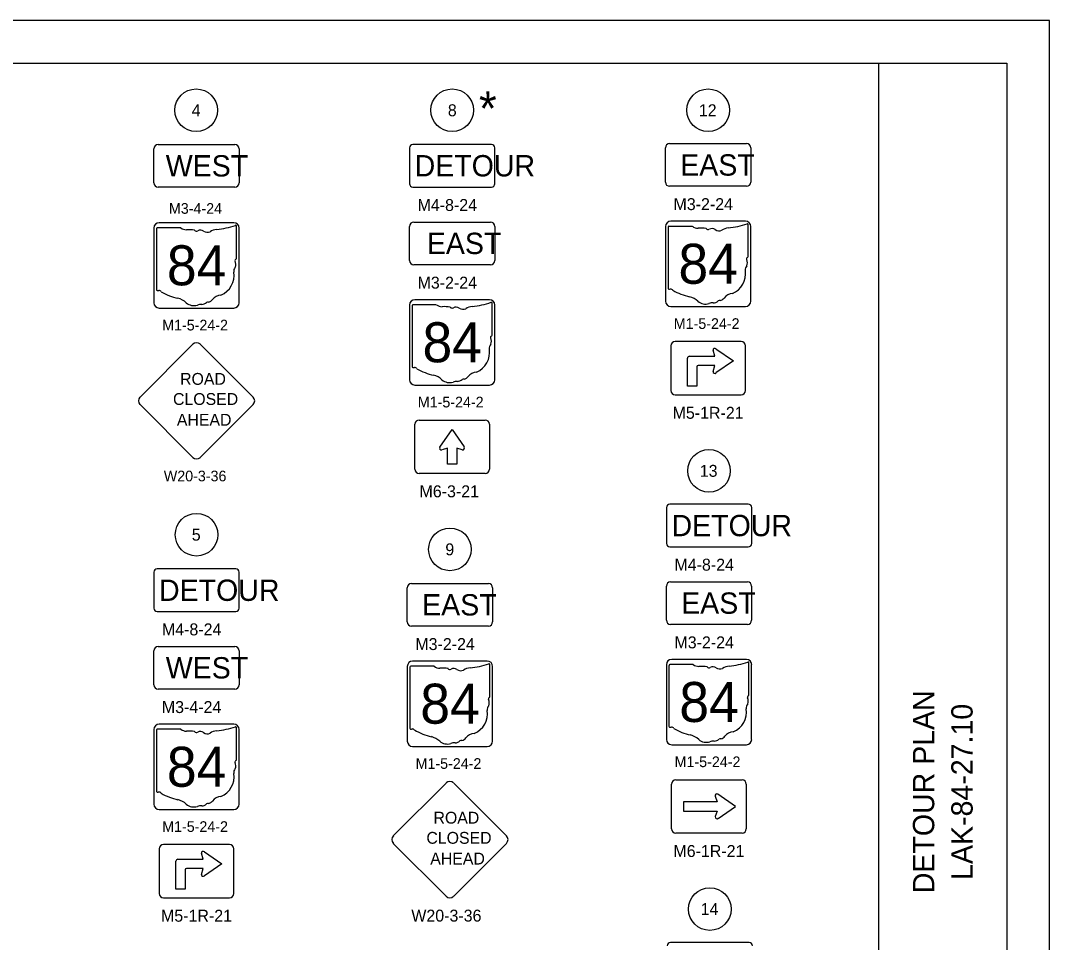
# Model space of a CAD drawing. Extents: x 0 to 54.8, y 0 to 22.
# Drawn here: x 21.94 to 34, y 11.2 to 22 of the extents above; entities that cross this region are included whole.
import ezdxf

# ---------------------------------------------------------------- set-up
doc = ezdxf.new("R2010")
doc.units = 0
for name, color, linetype in [('GM_X_Adjacent_County', 7, 'Continuous'), ('GM_X_County', 7, 'Continuous'), ('GM_X_County_Road', 7, 'Continuous'), ('GM_X_Minor_River_Text', 7, 'Continuous'), ('GM_X_Township', 7, 'Continuous')]:
    doc.layers.add(name, color=color, linetype=linetype)

msp = doc.modelspace()

# ---------------------------------------------------------------- linework, layer by layer
at = {"layer": 'GM_X_County'}
msp.add_lwpolyline([(0, 0), (34, 0), (34, 22), (0, 22)], close=True, dxfattribs=at)
at = {"layer": 'GM_X_County_Road'}
for centre in [(24, 20.949), (27, 20.949), (30, 20.949), (30.01, 16.724), (24.004, 15.976), (26.974, 15.804), (30.02, 11.589)]:
    msp.add_circle(centre, 0.25, dxfattribs=at)
at = {"layer": 'GM_X_Minor_River_Text'}
for p, q in [((23.554, 20.548), (24.454, 20.548)), ((29.499, 20.108), (29.499, 20.508)), ((29.549, 20.558), (30.449, 20.558)), ((30.499, 20.508), (30.499, 20.108)), ((23.504, 20.098), (23.504, 20.498)), ((24.504, 20.498), (24.504, 20.098)), ((24.454, 20.048), (23.554, 20.048)), ((30.449, 20.058), (29.549, 20.058)), ((23.534, 19.559), (23.534, 18.848)), ((23.818, 19.571), (23.544, 19.571)), ((24.472, 19.217), (24.472, 19.589)), ((26.5, 19.189), (26.5, 19.589)), ((26.55, 19.639), (27.45, 19.639)), ((27.5, 19.589), (27.5, 19.189)), ((29.531, 19.577), (29.531, 18.865)), ((29.814, 19.589), (29.54, 19.589)), ((30.468, 19.235), (30.468, 19.607)), ((24.472, 19.217), (24.472, 19.217)), ((30.468, 19.235), (30.468, 19.235)), ((27.45, 19.139), (26.55, 19.139)), ((26.531, 18.657), (26.531, 17.945)), ((26.814, 18.669), (26.54, 18.669)), ((27.468, 18.315), (27.468, 18.687)), ((27.468, 18.315), (27.468, 18.315)), ((30.387, 18.239), (29.612, 18.239)), ((29.562, 18.189), (29.562, 17.664)), ((30.078, 18.067), (30.057, 18.137)), ((30.092, 18.152), (30.296, 18.013)), ((30.437, 17.664), (30.437, 18.189)), ((29.757, 17.716), (29.757, 18.044)), ((29.781, 18.067), (30.078, 18.067)), ((29.781, 18.067), (29.781, 18.067)), ((30.296, 18.013), (30.092, 17.873)), ((29.867, 17.942), (29.867, 17.716)), ((30.078, 17.958), (29.882, 17.958)), ((30.057, 17.887), (30.078, 17.958)), ((29.612, 17.614), (30.387, 17.614)), ((29.867, 17.716), (29.757, 17.716)), ((26.562, 16.744), (26.562, 17.269)), ((26.612, 17.319), (27.387, 17.319)), ((27.437, 17.269), (27.437, 16.744)), ((26.857, 17.003), (26.999, 17.21)), ((26.999, 17.21), (27.139, 17.006)), ((26.945, 16.991), (26.881, 16.971)), ((26.945, 16.803), (26.945, 16.991)), ((27.118, 16.971), (27.054, 16.991)), ((27.054, 16.991), (27.054, 16.803)), ((27.054, 16.803), (26.945, 16.803)), ((27.387, 16.694), (26.612, 16.694)), ((26.474, 14.954), (26.474, 15.354)), ((26.524, 15.404), (27.424, 15.404)), ((27.474, 15.354), (27.474, 14.954)), ((29.51, 14.974), (29.51, 15.374)), ((29.56, 15.424), (30.46, 15.424)), ((30.51, 15.374), (30.51, 14.974)), ((27.424, 14.904), (26.524, 14.904)), ((30.46, 14.924), (29.56, 14.924)), ((23.504, 14.216), (23.504, 14.616)), ((23.554, 14.666), (24.454, 14.666)), ((24.504, 14.616), (24.504, 14.216)), ((30.478, 14.1), (30.478, 14.472)), ((26.504, 14.422), (26.504, 13.71)), ((26.788, 14.434), (26.514, 14.434)), ((27.442, 14.08), (27.442, 14.452)), ((29.541, 14.442), (29.541, 13.73)), ((29.825, 14.454), (29.55, 14.454)), ((24.454, 14.166), (23.554, 14.166)), ((27.442, 14.08), (27.442, 14.08)), ((30.478, 14.1), (30.478, 14.1)), ((23.534, 13.684), (23.534, 12.972)), ((23.818, 13.696), (23.544, 13.696)), ((24.472, 13.341), (24.472, 13.714)), ((24.472, 13.341), (24.472, 13.341)), ((29.572, 12.529), (29.572, 13.054)), ((29.622, 13.104), (30.397, 13.104)), ((30.447, 13.054), (30.447, 12.529)), ((30.084, 12.91), (30.104, 12.846)), ((30.322, 12.792), (30.115, 12.934)), ((30.104, 12.846), (29.713, 12.846)), ((29.713, 12.846), (29.713, 12.737)), ((30.118, 12.652), (30.322, 12.792)), ((29.713, 12.737), (30.104, 12.737)), ((30.104, 12.737), (30.084, 12.673)), ((30.397, 12.479), (29.622, 12.479)), ((24.391, 12.346), (23.616, 12.346)), ((23.566, 12.296), (23.566, 11.771)), ((24.081, 12.174), (24.061, 12.244)), ((24.096, 12.259), (24.3, 12.119)), ((24.441, 11.771), (24.441, 12.296)), ((23.761, 11.822), (23.761, 12.15)), ((23.785, 12.174), (24.081, 12.174)), ((23.785, 12.174), (23.785, 12.174)), ((24.081, 12.064), (23.886, 12.064)), ((24.061, 11.994), (24.081, 12.064)), ((24.3, 12.119), (24.096, 11.979)), ((23.871, 12.049), (23.871, 11.822)), ((23.871, 11.822), (23.761, 11.822)), ((23.616, 11.721), (24.391, 11.721))]:
    msp.add_line(p, q, dxfattribs=at)
for points in [[(26.5, 20.509), (26.5, 20.089)], [(27.46, 20.549), (26.54, 20.549)], [(27.5, 20.089), (27.5, 20.509)], [(26.54, 20.049), (27.46, 20.049)], [(23.504, 19.569), (23.504, 18.694)], [(24.441, 19.631), (23.566, 19.631)], [(24.504, 18.694), (24.504, 19.569)], [(29.5, 19.587), (29.5, 18.712)], [(30.438, 19.649), (29.562, 19.649)], [(30.5, 18.712), (30.5, 19.587)], [(27.438, 18.729), (26.562, 18.729)], [(23.566, 18.631), (24.441, 18.631)], [(26.5, 18.667), (26.5, 17.792)], [(27.5, 17.792), (27.5, 18.667)], [(29.562, 18.649), (30.438, 18.649)], [(23.341, 17.589), (23.96, 18.207)], [(24.048, 18.207), (24.667, 17.589)], [(26.562, 17.729), (27.438, 17.729)], [(23.96, 16.882), (23.341, 17.5)], [(24.667, 17.5), (24.048, 16.882)], [(29.511, 16.293), (29.511, 15.873)], [(30.471, 16.333), (29.551, 16.333)], [(30.511, 15.873), (30.511, 16.293)], [(29.551, 15.833), (30.471, 15.833)], [(24.463, 15.575), (23.543, 15.575)], [(23.503, 15.535), (23.503, 15.115)], [(24.503, 15.115), (24.503, 15.535)], [(23.543, 15.075), (24.463, 15.075)], [(27.411, 14.494), (26.536, 14.494)], [(30.448, 14.514), (29.573, 14.514)], [(26.474, 14.432), (26.474, 13.557)], [(27.474, 13.557), (27.474, 14.432)], [(29.51, 14.452), (29.51, 13.577)], [(30.51, 13.577), (30.51, 14.452)], [(24.441, 13.756), (23.566, 13.756)], [(23.504, 13.693), (23.504, 12.818)], [(24.504, 12.818), (24.504, 13.693)], [(29.573, 13.514), (30.448, 13.514)], [(26.536, 13.494), (27.411, 13.494)], [(26.31, 12.447), (26.929, 13.066)], [(27.018, 13.066), (27.636, 12.447)], [(23.566, 12.756), (24.441, 12.756)], [(26.929, 11.74), (26.31, 12.359)], [(27.636, 12.359), (27.018, 11.74)], [(30.48, 11.198), (29.56, 11.198)]]:
    msp.add_lwpolyline(points, dxfattribs=at)
for centre, radius, start, end in [((23.554, 20.498), 0.05, 90, 180), ((24.454, 20.498), 0.05, 0, 90), ((26.54, 20.509), 0.04, 90, 180), ((27.46, 20.509), 0.04, 0, 90), ((29.549, 20.508), 0.05, 90, 180), ((30.449, 20.508), 0.05, 0, 90), ((23.554, 20.098), 0.05, 180, 270), ((24.454, 20.098), 0.05, 270, 0), ((26.54, 20.089), 0.04, 180, 270), ((27.46, 20.089), 0.04, 270, 0), ((29.549, 20.108), 0.05, 180, 270), ((30.449, 20.108), 0.05, 270, 0), ((23.566, 19.569), 0.0625, 90, 180), ((23.545, 19.561), 0.0109, 98.1301, 188.1301), ((23.884, 19.654), 0.105, 231.6195, 271.1119), ((23.919, 19.172), 0.378, 80.4867, 94.9883), ((24.004, 19.564), 0.0304, 219.7921, 297.1024), ((24.049, 19.482), 0.0632, 54.4667, 119.1411), ((24.265, 19.354), 0.2, 97.3462, 120.7689), ((24.138, 20.541), 0.994, 275.8445, 288.9065), ((24.441, 19.569), 0.0625, 0, 90), ((24.462, 19.591), 0.0104, 351.8621, 97.738), ((26.55, 19.589), 0.05, 90, 180), ((27.45, 19.589), 0.05, 0, 90), ((29.562, 19.587), 0.0625, 90, 180), ((29.541, 19.579), 0.0109, 98.1301, 188.1301), ((29.88, 19.672), 0.105, 231.6195, 271.1119), ((29.915, 19.19), 0.378, 80.4867, 94.9883), ((30, 19.582), 0.0304, 219.7921, 297.1024), ((30.045, 19.5), 0.0632, 54.4667, 119.1411), ((30.127, 19.613), 0.076, 233.8562, 294.8282), ((30.261, 19.372), 0.2, 97.3462, 120.7689), ((30.134, 20.559), 0.994, 275.8445, 288.9065), ((30.438, 19.587), 0.0625, 0, 90), ((30.458, 19.608), 0.0104, 351.8621, 97.738), ((24.131, 19.595), 0.076, 233.8562, 294.8282), ((24.47, 19.189), 0.0162, 107.944, 210.337), ((24.367, 19.142), 0.097, 340.033, 23.6496), ((24.461, 19.215), 0.0112, 289.6038, 7.7341), ((26.55, 19.189), 0.05, 180, 270), ((27.45, 19.189), 0.05, 270, 0), ((30.466, 19.207), 0.0162, 107.944, 210.337), ((30.363, 19.16), 0.097, 340.033, 23.6496), ((30.457, 19.233), 0.0112, 289.6038, 7.7341), ((24.509, 19.061), 0.0705, 136.8065, 186.9296), ((30.19, 19.032), 0.249, 292.3089, 8.9858), ((30.505, 19.079), 0.0705, 136.8065, 186.9296), ((24.194, 19.014), 0.249, 292.3089, 8.9858), ((23.545, 18.846), 0.011, 171.9584, 258.3066), ((23.547, 18.919), 0.0836, 267.339, 280.6039), ((23.564, 18.807), 0.0302, 29.7484, 93.2717), ((23.945, 19.446), 0.718, 240.4129, 257.1985), ((29.541, 18.864), 0.011, 171.9584, 258.3066), ((29.543, 18.937), 0.0836, 267.339, 280.6039), ((29.56, 18.824), 0.0302, 29.7484, 93.2717), ((29.941, 19.464), 0.718, 240.4129, 257.1985), ((23.566, 18.694), 0.0625, 180, 270), ((23.731, 18.528), 0.225, 47.1842, 75.836), ((23.974, 18.803), 0.143, 230.7004, 286.2918), ((24.066, 18.75), 0.0759, 268.777, 315.5493), ((24.135, 18.681), 0.0214, 65.7517, 132.6484), ((24.126, 18.779), 0.0803, 282.8732, 323.2771), ((24.299, 18.648), 0.136, 94.4031, 142.5768), ((24.441, 18.694), 0.0625, 270, 0), ((26.562, 18.667), 0.0625, 90, 180), ((27.134, 19.639), 0.994, 275.8445, 288.9065), ((27.438, 18.667), 0.0625, 0, 90), ((27.458, 18.688), 0.0104, 351.8621, 97.738), ((29.562, 18.712), 0.0625, 180, 270), ((29.727, 18.546), 0.225, 47.1842, 75.836), ((29.97, 18.821), 0.143, 230.7004, 286.2918), ((30.052, 18.575), 0.117, 85.6951, 111.2099), ((30.062, 18.768), 0.0759, 268.777, 315.5493), ((30.131, 18.699), 0.0214, 65.7517, 132.6484), ((30.122, 18.797), 0.0803, 282.8732, 323.2771), ((30.295, 18.666), 0.136, 94.4031, 142.5768), ((30.438, 18.712), 0.0625, 270, 0), ((24.056, 18.557), 0.117, 85.6951, 111.2099), ((26.541, 18.659), 0.0109, 98.1301, 188.1301), ((26.88, 18.752), 0.105, 231.6195, 271.1119), ((26.915, 18.27), 0.378, 80.4867, 94.9883), ((27, 18.662), 0.0304, 219.7921, 297.1024), ((27.045, 18.58), 0.0632, 54.4667, 119.1411), ((27.127, 18.693), 0.076, 233.8562, 294.8282), ((27.261, 18.452), 0.2, 97.3462, 120.7689), ((24.004, 18.163), 0.0625, 45, 135), ((27.466, 18.287), 0.0162, 107.944, 210.337), ((27.363, 18.24), 0.097, 340.033, 23.6496), ((27.457, 18.313), 0.0112, 289.6038, 7.7341), ((29.612, 18.189), 0.05, 90, 180), ((30.387, 18.189), 0.05, 0, 90), ((27.19, 18.112), 0.249, 292.3089, 8.9858), ((27.505, 18.159), 0.0705, 136.8065, 186.9296), ((30.078, 18.137), 0.0209, 45.0001, 179.9983), ((29.781, 18.044), 0.0234, 90, 180), ((26.541, 17.944), 0.011, 171.9584, 258.3066), ((26.543, 18.017), 0.0836, 267.339, 280.6039), ((26.56, 17.904), 0.0302, 29.7484, 93.2717), ((26.941, 18.544), 0.718, 240.4129, 257.1985), ((27.295, 17.746), 0.136, 94.4031, 142.5768), ((29.882, 17.942), 0.0156, 90, 180), ((30.078, 17.887), 0.0209, 179.9983, 314.9999), ((26.562, 17.792), 0.0625, 180, 270), ((26.727, 17.626), 0.225, 47.1842, 75.836), ((26.97, 17.901), 0.143, 230.7004, 286.2918), ((27.052, 17.655), 0.117, 85.6951, 111.2099), ((27.062, 17.848), 0.0759, 268.777, 315.5493), ((27.131, 17.779), 0.0214, 65.7517, 132.6484), ((27.122, 17.877), 0.0803, 282.8732, 323.2771), ((27.438, 17.792), 0.0625, 270, 0), ((29.612, 17.664), 0.05, 180, 270), ((30.387, 17.664), 0.05, 270, 0), ((23.385, 17.545), 0.0625, 135, 225), ((24.623, 17.545), 0.0625, 315, 45), ((26.612, 17.269), 0.05, 90, 180), ((27.387, 17.269), 0.05, 0, 90), ((27.124, 16.991), 0.0209, 252.7954, 45.0096), ((26.874, 16.991), 0.0209, 145.4112, 287.2046), ((24.004, 16.926), 0.0625, 225, 315), ((26.612, 16.744), 0.05, 180, 270), ((27.387, 16.744), 0.05, 270, 0), ((29.551, 16.293), 0.04, 90, 180), ((30.471, 16.293), 0.04, 0, 90), ((29.551, 15.873), 0.04, 180, 270), ((30.471, 15.873), 0.04, 270, 0), ((23.543, 15.535), 0.04, 90, 180), ((24.463, 15.535), 0.04, 0, 90), ((26.524, 15.354), 0.05, 90, 180), ((27.424, 15.354), 0.05, 0, 90), ((29.56, 15.374), 0.05, 90, 180), ((30.46, 15.374), 0.05, 0, 90), ((23.543, 15.115), 0.04, 180, 270), ((24.463, 15.115), 0.04, 270, 0), ((26.524, 14.954), 0.05, 180, 270), ((27.424, 14.954), 0.05, 270, 0), ((29.56, 14.974), 0.05, 180, 270), ((30.46, 14.974), 0.05, 270, 0), ((23.554, 14.616), 0.05, 90, 180), ((24.454, 14.616), 0.05, 0, 90), ((26.536, 14.432), 0.0625, 90, 180), ((27.411, 14.432), 0.0625, 0, 90), ((29.573, 14.452), 0.0625, 90, 180), ((30.144, 15.424), 0.994, 275.8445, 288.9065), ((30.448, 14.452), 0.0625, 0, 90), ((30.468, 14.473), 0.0104, 351.8621, 97.738), ((26.515, 14.424), 0.0109, 98.1301, 188.1301), ((26.854, 14.517), 0.105, 231.6195, 271.1119), ((26.889, 14.035), 0.378, 80.4867, 94.9883), ((26.974, 14.427), 0.0304, 219.7921, 297.1024), ((27.019, 14.345), 0.0632, 54.4667, 119.1411), ((27.101, 14.458), 0.076, 233.8562, 294.8282), ((27.235, 14.217), 0.2, 97.3462, 120.7689), ((27.108, 15.404), 0.994, 275.8445, 288.9065), ((27.432, 14.453), 0.0104, 351.8621, 97.738), ((29.552, 14.444), 0.0109, 98.1301, 188.1301), ((29.89, 14.537), 0.105, 231.6195, 271.1119), ((29.925, 14.055), 0.378, 80.4867, 94.9883), ((30.011, 14.447), 0.0304, 219.7921, 297.1024), ((30.056, 14.365), 0.0632, 54.4667, 119.1411), ((30.137, 14.478), 0.076, 233.8562, 294.8282), ((30.271, 14.237), 0.2, 97.3462, 120.7689), ((23.554, 14.216), 0.05, 180, 270), ((24.454, 14.216), 0.05, 270, 0), ((27.44, 14.052), 0.0162, 107.944, 210.337), ((27.337, 14.005), 0.097, 340.033, 23.6496), ((27.431, 14.078), 0.0112, 289.6038, 7.7341), ((30.516, 13.944), 0.0705, 136.8065, 186.9296), ((30.476, 14.072), 0.0162, 107.944, 210.337), ((30.373, 14.025), 0.097, 340.033, 23.6496), ((30.467, 14.098), 0.0112, 289.6038, 7.7341), ((27.164, 13.877), 0.249, 292.3089, 8.9858), ((27.479, 13.924), 0.0705, 136.8065, 186.9296), ((30.2, 13.897), 0.249, 292.3089, 8.9858), ((23.566, 13.693), 0.0625, 90, 180), ((24.441, 13.693), 0.0625, 0, 90), ((23.545, 13.685), 0.0109, 98.1301, 188.1301), ((23.884, 13.779), 0.105, 231.6195, 271.1119), ((23.919, 13.297), 0.378, 80.4867, 94.9883), ((24.004, 13.689), 0.0304, 219.7921, 297.1024), ((24.049, 13.607), 0.0632, 54.4667, 119.1411), ((24.131, 13.719), 0.076, 233.8562, 294.8282), ((24.265, 13.479), 0.2, 97.3462, 120.7689), ((24.138, 14.666), 0.994, 275.8445, 288.9065), ((24.462, 13.715), 0.0104, 351.8621, 97.738), ((26.515, 13.709), 0.011, 171.9584, 258.3066), ((26.517, 13.782), 0.0836, 267.339, 280.6039), ((26.534, 13.669), 0.0302, 29.7484, 93.2717), ((26.915, 14.309), 0.718, 240.4129, 257.1985), ((27.269, 13.511), 0.136, 94.4031, 142.5768), ((29.552, 13.729), 0.011, 171.9584, 258.3066), ((29.553, 13.802), 0.0836, 267.339, 280.6039), ((29.571, 13.689), 0.0302, 29.7484, 93.2717), ((29.951, 14.329), 0.718, 240.4129, 257.1985), ((29.737, 13.411), 0.225, 47.1842, 75.836), ((30.305, 13.531), 0.136, 94.4031, 142.5768), ((26.536, 13.557), 0.0625, 180, 270), ((26.701, 13.391), 0.225, 47.1842, 75.836), ((26.944, 13.666), 0.143, 230.7004, 286.2918), ((27.026, 13.42), 0.117, 85.6951, 111.2099), ((27.036, 13.613), 0.0759, 268.777, 315.5493), ((27.105, 13.544), 0.0214, 65.7517, 132.6484), ((27.096, 13.642), 0.0803, 282.8732, 323.2771), ((27.411, 13.557), 0.0625, 270, 0), ((29.573, 13.577), 0.0625, 180, 270), ((29.98, 13.686), 0.143, 230.7004, 286.2918), ((30.062, 13.44), 0.117, 85.6951, 111.2099), ((30.073, 13.633), 0.0759, 268.777, 315.5493), ((30.142, 13.564), 0.0214, 65.7517, 132.6484), ((30.132, 13.662), 0.0803, 282.8732, 323.2771), ((30.448, 13.577), 0.0625, 270, 0), ((24.47, 13.314), 0.0162, 107.944, 210.337), ((24.367, 13.267), 0.097, 340.033, 23.6496), ((24.461, 13.34), 0.0112, 289.6038, 7.7341), ((24.194, 13.138), 0.249, 292.3089, 8.9858), ((24.509, 13.186), 0.0705, 136.8065, 186.9296), ((26.973, 13.022), 0.0625, 45, 135), ((29.622, 13.054), 0.05, 90, 180), ((30.397, 13.054), 0.05, 0, 90), ((23.545, 12.971), 0.011, 171.9584, 258.3066), ((23.547, 13.043), 0.0836, 267.339, 280.6039), ((23.564, 12.931), 0.0302, 29.7484, 93.2717), ((23.945, 13.57), 0.718, 240.4129, 257.1985), ((24.299, 12.772), 0.136, 94.4031, 142.5768), ((30.104, 12.917), 0.0209, 55.4112, 197.2046), ((23.566, 12.818), 0.0625, 180, 270), ((23.731, 12.653), 0.225, 47.1842, 75.836), ((23.974, 12.928), 0.143, 230.7004, 286.2918), ((24.056, 12.682), 0.117, 85.6951, 111.2099), ((24.066, 12.874), 0.0759, 268.777, 315.5493), ((24.135, 12.805), 0.0214, 65.7517, 132.6484), ((24.126, 12.903), 0.0803, 282.8732, 323.2771), ((24.441, 12.818), 0.0625, 270, 0), ((30.104, 12.667), 0.0209, 162.7954, 315.0096), ((26.355, 12.403), 0.0625, 135, 225), ((27.592, 12.403), 0.0625, 315, 45), ((29.622, 12.529), 0.05, 180, 270), ((30.397, 12.529), 0.05, 270, 360), ((23.616, 12.296), 0.05, 90, 180), ((24.391, 12.296), 0.05, 0, 90), ((24.081, 12.244), 0.0209, 45.0001, 179.9983), ((23.785, 12.15), 0.0234, 90, 180), ((23.886, 12.049), 0.0156, 90, 180), ((24.081, 11.994), 0.0209, 179.9983, 314.9999), ((23.616, 11.771), 0.05, 180, 270), ((24.391, 11.771), 0.05, 270, 0), ((26.973, 11.784), 0.0625, 225, 315), ((29.56, 11.158), 0.04, 90, 180), ((30.48, 11.158), 0.04, 0, 90)]:
    msp.add_arc(centre, radius, start, end, dxfattribs=at)
at = {"layer": 'GM_X_Township'}
msp.add_line((32, 0.5), (32, 21.5), dxfattribs=at)
msp.add_lwpolyline([(1.5, 21.5), (33.5, 21.5), (33.5, 0.5), (1.5, 0.5)], close=True, dxfattribs=at)

# ---------------------------------------------------------------- texts
at = {"layer": 'GM_X_Adjacent_County'}
for s, p in [('DETOUR PLAN', (32.65, 11.775)), ('LAK-84-27.10', (33.1, 11.931))]:
    msp.add_text(s, height=0.25, rotation=90, dxfattribs=at).set_placement(p)
at = {"layer": 'GM_X_County_Road'}
for s, height, p in [('*', 0.4, (27.314, 20.771)), ('4', 0.14, (23.947, 20.879)), ('8', 0.14, (26.949, 20.879)), ('12', 0.14, (29.891, 20.879)), ('M4-8-24', 0.14, (26.594, 19.769)), ('M3-2-24', 0.14, (29.594, 19.779)), ('M3-4-24', 0.125, (23.68, 19.736)), ('M3-2-24', 0.14, (26.594, 18.859)), ('M1-5-24-2', 0.125, (23.601, 18.369)), ('M1-5-24-2', 0.125, (29.597, 18.387)), ('M1-5-24-2', 0.125, (26.597, 17.467)), ('M5-1R-21', 0.14, (29.583, 17.334)), ('13', 0.14, (29.902, 16.654)), ('W20-3-36', 0.125, (23.62, 16.601)), ('M6-3-21', 0.14, (26.617, 16.414)), ('5', 0.14, (23.948, 15.906)), ('9', 0.14, (26.92, 15.734)), ('M4-8-24', 0.14, (29.605, 15.554)), ('M4-8-24', 0.14, (23.598, 14.796)), ('M3-2-24', 0.14, (26.568, 14.624)), ('M3-2-24', 0.14, (29.605, 14.644)), ('M3-4-24', 0.14, (23.597, 13.886)), ('M1-5-24-2', 0.125, (26.571, 13.232)), ('M1-5-24-2', 0.125, (29.607, 13.252)), ('M1-5-24-2', 0.125, (23.601, 12.493)), ('M6-1R-21', 0.14, (29.593, 12.199)), ('M5-1R-21', 0.14, (23.587, 11.441)), ('W20-3-36', 0.14, (26.521, 11.442)), ('14', 0.14, (29.912, 11.519))]:
    msp.add_text(s, height=height, dxfattribs=at).set_placement(p)
at = {"layer": 'GM_X_Minor_River_Text'}
for s, height, p in [('WEST', 0.25, (23.643, 20.173)), ('DETOUR', 0.25, (26.56, 20.174)), ('EAST', 0.25, (29.673, 20.183)), ('EAST', 0.25, (26.703, 19.264)), ('84', 0.4688, (23.656, 18.898)), ('84', 0.4688, (29.652, 18.916)), ('84', 0.4688, (26.652, 17.996)), ('ROAD', 0.1389, (23.811, 17.732)), ('CLOSED', 0.1389, (23.728, 17.496)), ('AHEAD', 0.1389, (23.773, 17.253)), ('DETOUR', 0.25, (29.571, 15.958)), ('DETOUR', 0.25, (23.564, 15.2)), ('EAST', 0.25, (26.648, 15.029)), ('EAST', 0.25, (29.684, 15.049)), ('WEST', 0.25, (23.643, 14.291)), ('84', 0.4688, (26.626, 13.761)), ('84', 0.4688, (29.662, 13.781)), ('84', 0.4688, (23.656, 13.022)), ('ROAD', 0.1389, (26.781, 12.59)), ('CLOSED', 0.1389, (26.698, 12.354)), ('AHEAD', 0.1389, (26.743, 12.111))]:
    msp.add_text(s, height=height, dxfattribs=at).set_placement(p)

doc.saveas('drawing.dxf')
